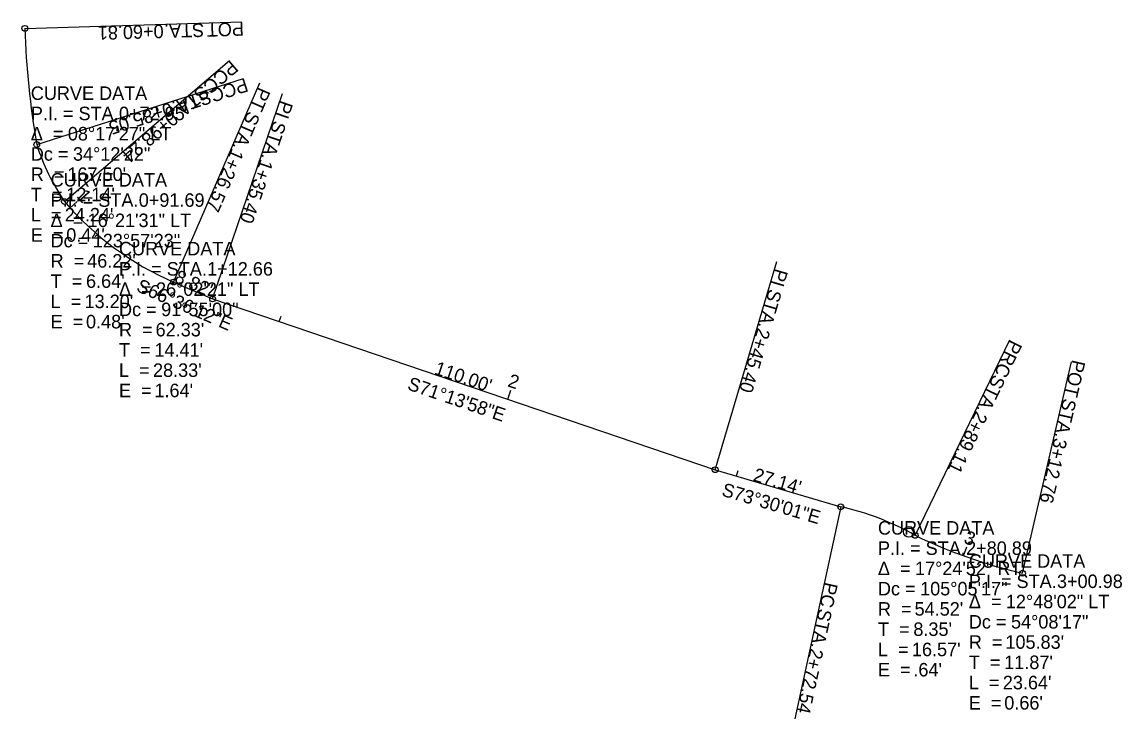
# Model space of a CAD drawing. Extents: x 2377933 to 2378161, y 253638 to 253783.
import ezdxf

# ---------------------------------------------------------------- set-up
doc = ezdxf.new("R2010")
doc.units = 0
for name, color, linetype in [('_CIVIL_CONSTRUCTION', 7, 'Continuous'), ('GT_Project_Soil_Boring', 7, 'Continuous'), ('MD_X_Asphalt_Pavement', 7, 'Continuous'), ('PF_X_Ground_Line', 7, 'Continuous'), ('SV_X_Control_Cells_Found', 7, 'Continuous'), ('SV_X_Random_Point', 7, 'Continuous'), ('UT_X_Cable_TV_FO', 7, 'Continuous')]:
    doc.layers.add(name, color=color, linetype=linetype)

msp = doc.modelspace()

# ---------------------------------------------------------------- linework, layer by layer
at = {"layer": 'MD_X_Asphalt_Pavement'}
msp.add_circle((2378116.8, 253677.23), 1.12, dxfattribs=at)
at = {"layer": 'PF_X_Ground_Line'}
for p, q in [((2377964.4, 253729.02), (2377972.5, 253725.51)), ((2377972.5, 253725.51), (2378076.65, 253690.12)), ((2378076.65, 253690.12), (2378102.68, 253682.42))]:
    msp.add_line(p, q, dxfattribs=at)
for centre, radius, start, end in [((2378101.03, 253786.5), 167.5, 181.6706, 189.9615), ((2377980.07, 253771.6), 46.22, 197.7367, 214.0953), ((2377989.15, 253786.23), 62.33, 220.5641, 246.6033), ((2378091.12, 253629.13), 54.52, 60.3478, 77.7624), ((2378164.23, 253771.76), 105.83, 244.1565, 256.957)]:
    msp.add_arc(centre, radius, start, end, dxfattribs=at)
at = {"layer": 'SV_X_Control_Cells_Found'}
for p, q in [((2377933.59, 253781.61), (2377978.58, 253782.93)), ((2377941.8, 253745.69), (2377975.98, 253774.95)), ((2377936.05, 253757.52), (2377978.91, 253771.23)), ((2377964.4, 253729.02), (2377982.27, 253770.32)), ((2377972.5, 253725.51), (2377986.97, 253768.12)), ((2378076.65, 253690.12), (2378089.43, 253733.27)), ((2378118.09, 253676.51), (2378137.71, 253717.01)), ((2378140.34, 253668.66), (2378150.5, 253712.5)), ((2378102.68, 253682.42), (2378093.14, 253638.44))]:
    msp.add_line(p, q, dxfattribs=at)
for centre in [(2377933.59, 253781.61), (2377936.05, 253757.52), (2377941.8, 253745.69), (2377964.4, 253729.02), (2377972.5, 253725.51), (2378076.65, 253690.12), (2378102.68, 253682.42), (2378118.09, 253676.51), (2378140.34, 253668.66)]:
    msp.add_circle(centre, 0.6, dxfattribs=at)
at = {"layer": 'SV_X_Random_Point'}
for p, q in [((2377942.96, 253744.37), (2377944.44, 253745.72)), ((2377986.32, 253720.82), (2377986.71, 253721.95)), ((2378033.66, 253704.73), (2378034.31, 253706.62)), ((2378081.06, 253688.82), (2378081.4, 253689.97)), ((2378128.12, 253672.28), (2378128.8, 253674.16))]:
    msp.add_line(p, q, dxfattribs=at)

# ---------------------------------------------------------------- texts
at = {"layer": '_CIVIL_CONSTRUCTION'}
for s, rotation, p in [('S66°36\'12"E', 336.6033, (2377956.5, 253727.2)), ('S71°13\'58"E', 341.2328, (2378012.67, 253706.79)), ('S73°30\'01"E', 343.5004, (2378077.81, 253684.77))]:
    msp.add_text(s, height=2.8, rotation=rotation, dxfattribs=at).set_placement(p)
at = {"layer": 'GT_Project_Soil_Boring'}
for s, p in [('CURVE DATA', (2377934.82, 253766.77)), ('P.I. = STA. ', (2377934.82, 253762.57)), ('0+72.95', (2377953.09, 253762.57)), ('Δ  = ', (2377934.82, 253758.37)), ('08°17\'27" LT', (2377942.5, 253758.37)), ('Dc = ', (2377934.82, 253754.17)), ('34°12\'22"', (2377943.56, 253754.17)), ('R  = ', (2377934.82, 253749.97)), ("167.50'", (2377942.4, 253749.97)), ('CURVE DATA', (2377938.92, 253748.81)), ('T  = ', (2377934.82, 253745.77)), ("12.14'", (2377942.16, 253745.77)), ('P.I. = STA. ', (2377938.92, 253744.61)), ('0+91.69', (2377957.19, 253744.61)), ('L  = ', (2377934.82, 253741.57)), ("24.24'", (2377941.86, 253741.57)), ('Δ  = ', (2377938.92, 253740.41)), ('16°21\'31" LT', (2377946.6, 253740.41)), ('E  = ', (2377934.82, 253737.37)), ('Dc = ', (2377938.92, 253736.21)), ("0.44'", (2377942.16, 253737.37)), ('123°57\'23"', (2377947.66, 253736.21)), ('CURVE DATA', (2377953.1, 253734.55)), ('R  = ', (2377938.92, 253732.01)), ("46.22'", (2377946.5, 253732.01)), ('P.I. = STA. ', (2377953.1, 253730.35)), ('1+12.66', (2377971.36, 253730.35)), ('T  = ', (2377938.92, 253727.81)), ("6.64'", (2377946.26, 253727.81)), ('Δ  = ', (2377953.1, 253726.15)), ('26°02\'21" LT', (2377960.77, 253726.15)), ('L  = ', (2377938.92, 253723.61)), ("13.20'", (2377945.96, 253723.61)), ('Dc = ', (2377953.1, 253721.95)), ('91°55\'00"', (2377961.84, 253721.95)), ('E  = ', (2377938.92, 253719.41)), ("0.48'", (2377946.26, 253719.41)), ('R  = ', (2377953.1, 253717.75)), ("62.33'", (2377960.68, 253717.75)), ('T  = ', (2377953.1, 253713.55)), ("14.41'", (2377960.44, 253713.55)), ('L  = ', (2377953.1, 253709.35)), ("28.33'", (2377960.14, 253709.35)), ('E  = ', (2377953.1, 253705.15)), ("1.64'", (2377960.44, 253705.15)), ('CURVE DATA', (2378110.38, 253676.66)), ('P.I. = STA. ', (2378110.38, 253672.46)), ('2+80.89', (2378128.65, 253672.46)), ('Δ  = ', (2378110.38, 253668.26)), ('17°24\'52" RT', (2378118.06, 253668.26)), ('CURVE DATA', (2378129.22, 253669.79)), ('P.I. = STA. ', (2378129.22, 253665.59)), ('3+00.98', (2378147.48, 253665.59)), ('Dc = ', (2378110.38, 253664.06)), ('105°05\'17"', (2378119.12, 253664.06)), ('Δ  = ', (2378129.22, 253661.39)), ('12°48\'02" LT', (2378136.89, 253661.39)), ('R  = ', (2378110.38, 253659.86)), ("54.52'", (2378117.97, 253659.86)), ('Dc = ', (2378129.22, 253657.19)), ('54°08\'17"', (2378137.96, 253657.19)), ('T  = ', (2378110.38, 253655.66)), ("8.35'", (2378117.72, 253655.66)), ('R  = ', (2378129.22, 253652.99)), ("105.83'", (2378136.8, 253652.99)), ('L  = ', (2378110.38, 253651.46)), ("16.57'", (2378117.42, 253651.46)), ('E  = ', (2378110.38, 253647.26)), (".64'", (2378117.72, 253647.26)), ('T  = ', (2378129.22, 253648.79)), ("11.87'", (2378136.55, 253648.79)), ('L  = ', (2378129.22, 253644.59)), ("23.64'", (2378136.26, 253644.59)), ("0.66'", (2378136.56, 253640.39)), ('E  = ', (2378129.22, 253640.39))]:
    msp.add_text(s, height=2.8, dxfattribs=at).set_placement(p)
at = {"layer": 'SV_X_Control_Cells_Found'}
for s, rotation, p in [('0+60.81', 181.6706, (2377962.3, 253782.41)), (' STA. ', 181.6706, (2377971.75, 253782.68)), ('POT', 181.6706, (2377978.94, 253782.89)), ('PCC', 220.5641, (2377976.26, 253775.14)), ('PCC', 197.7367, (2377979.27, 253771.3)), (' STA. ', 197.7367, (2377972.71, 253769.2)), (' STA. ', 220.5641, (2377971.03, 253770.66)), ('PT', 246.6033, (2377982, 253769.6)), ('PI', 251.2328, (2377986.58, 253766.84)), ('0+85.05', 197.7367, (2377963.71, 253766.32)), ('0+98.24', 220.5641, (2377963.85, 253764.51)), (' STA. ', 246.6033, (2377980.25, 253765.55)), (' STA. ', 251.2328, (2377985.49, 253763.63)), ('1+26.57', 246.6033, (2377976.5, 253756.88)), ('1+35.40', 251.2328, (2377982.45, 253754.68)), ('PI', 253.5004, (2378089.09, 253731.97)), (' STA. ', 253.5004, (2378088.12, 253728.72)), ('2+45.40', 253.5004, (2378085.44, 253719.66)), ('PRC', 244.1565, (2378137.85, 253717.21)), ('POT', 256.957, (2378150.67, 253713.05)), (' STA. ', 244.1565, (2378134.82, 253710.96)), (' STA. ', 256.957, (2378149.04, 253706.04)), ('2+89.11', 244.1565, (2378130.7, 253702.46)), ('3+12.76', 256.957, (2378146.91, 253696.83)), ('PC', 257.7624, (2378099.36, 253666.95)), (' STA. ', 257.7624, (2378098.39, 253662.47)), ('2+72.54', 257.7624, (2378096.39, 253653.23))]:
    msp.add_text(s, height=2.8, rotation=rotation, dxfattribs=at).set_placement(p)
at = {"layer": 'SV_X_Random_Point'}
for s, rotation, p in [('1', 312.1781, (2377944.19, 253746.73)), ('2', 341.2328, (2378033.48, 253707.43)), ('3', 340.0506, (2378127.99, 253674.98))]:
    msp.add_text(s, height=2.8, rotation=rotation, dxfattribs=at).set_placement(p)
at = {"layer": 'UT_X_Cable_TV_FO'}
for s, rotation, p in [("8.82'", 336.6033, (2377964.38, 253729.07)), ("110.00'", 341.2328, (2378018.26, 253710.01)), ("27.14'", 343.5004, (2378084.33, 253687.87))]:
    msp.add_text(s, height=2.8, rotation=rotation, dxfattribs=at).set_placement(p)

doc.saveas('drawing.dxf')
